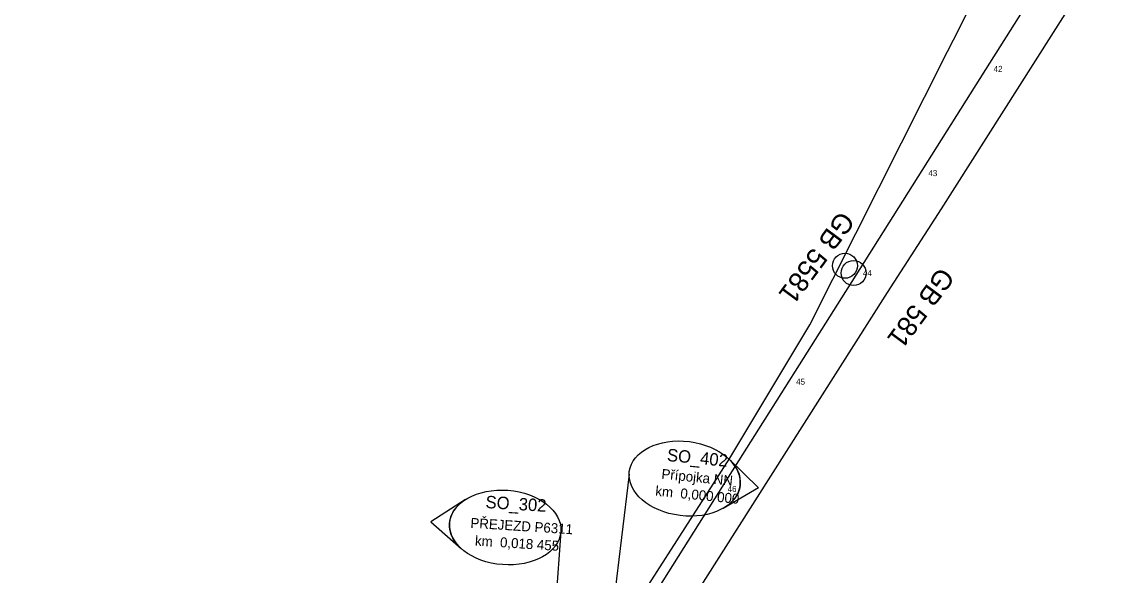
# Model space of a CAD drawing. Extents: x -743546 to -74, y -1128126 to -103.
# Drawn here: x -743267.3 to -743045.6, y -1127036 to -1126924.5 of the extents above; entities that cross this region are included whole.
import ezdxf

# ---------------------------------------------------------------- set-up
doc = ezdxf.new("R2010")
doc.units = 0
for name, color, linetype in [('_Násyp', 7, 'Continuous'), ('_Zabezpečovací zařízení_trasa', 7, 'Continuous'), ('bublina_fialová_čára_tenká', 7, 'Continuous'), ('bublina_růžová_230_čára_tučná', 7, 'Continuous'), ('křížky', 7, 'Continuous'), ('Vrstva 53', 7, 'Continuous'), ('Vrstva 60', 7, 'Continuous'), ('ŽBP', 7, 'Continuous')]:
    doc.layers.add(name, color=color, linetype=linetype)

# ---------------------------------------------------------------- blocks, each defined once
blk = doc.blocks.new('POINT_DISPLAY')
blk.add_line((0, 0), (0, 0))

msp = doc.modelspace()

# ---------------------------------------------------------------- linework, layer by layer
at = {"layer": '_Zabezpečovací zařízení_trasa'}
msp.add_lwpolyline([(-743049.28, -1126895.95), (-743072.49, -1126932.75), (-743098.65, -1126974.15), (-743125.94, -1127017.38), (-743152.6, -1127059.61), (-743175.02, -1127095.12), (-743199.16, -1127133.35), (-743215.97, -1127159.94), (-743232.82, -1127186.51), (-743247.46, -1127209.81), (-743254.52, -1127221.64), (-743261.3, -1127233.69), (-743264.16, -1127239.2), (-743264.86, -1127241.11), (-743267.34, -1127245.82)], dxfattribs=at)
at = {"layer": 'bublina_fialová_čára_tenká'}
for p, q in [((-743145.09, -1127015.48), (-743152.93, -1127080.48)), ((-743158.82, -1127027.04), (-743164.29, -1127099.42))]:
    msp.add_line(p, q, dxfattribs=at)
at = {"layer": 'bublina_růžová_230_čára_tučná'}
for p, q in [((-743124.92, -1127012.47), (-743119, -1127018.23)), ((-743124.92, -1127012.47), (-743119, -1127018.23)), ((-743119, -1127018.23), (-743126.16, -1127022.35)), ((-743119, -1127018.23), (-743126.16, -1127022.35)), ((-743178.06, -1127020.6), (-743185, -1127025.07)), ((-743178.06, -1127020.6), (-743185, -1127025.07)), ((-743185, -1127025.07), (-743178.81, -1127030.53)), ((-743185, -1127025.07), (-743178.81, -1127030.53))]:
    msp.add_line(p, q, dxfattribs=at)
for centre, major_axis in [((-743133.89, -1127016.36), (-11.16, 1.4)), ((-743170.04, -1127026.2), (11.22, -0.85))]:
    msp.add_ellipse(centre, major_axis=major_axis, ratio=0.666667, dxfattribs=at)
for centre, major_axis in [((-743133.89, -1127016.36), (11.16, -1.4)), ((-743170.04, -1127026.2), (-11.22, 0.85))]:
    msp.add_ellipse(centre, major_axis=major_axis, ratio=0.666473, start_param=5.557317, end_param=7.009053, dxfattribs=at)
at = {"layer": 'Vrstva 53'}
msp.add_lwpolyline([(-743032.8, -1126884.17), (-743063.8, -1126932.98), (-743082.27, -1126962.07), (-743093.1, -1126978.92), (-743136.47, -1127047.12), (-743147.78, -1127068.8), (-743159.64, -1127094.74), (-743160.17, -1127095.91), (-743166.78, -1127095.57), (-743176.42, -1127093.47), (-743180.17, -1127093.19), (-743180.08, -1127092.14), (-743178.51, -1127091.81), (-743175.35, -1127091.16), (-743150.08, -1127051.72), (-743124.8, -1127012.28), (-743108.67, -1126985.4), (-743080.97, -1126930.41), (-743079.79, -1126928.05), (-743048.51, -1126865.51)], dxfattribs=at)
at = {"layer": 'Vrstva 60'}
for p, q in [((-743072.49, -1126932.75), (-743072.49, -1126932.75)), ((-743085.57, -1126953.45), (-743085.57, -1126953.45)), ((-743098.65, -1126974.15), (-743098.65, -1126974.15)), ((-743112.29, -1126995.77), (-743112.29, -1126995.77)), ((-743125.94, -1127017.38), (-743125.94, -1127017.38))]:
    msp.add_line(p, q, dxfattribs=at)
at = {"layer": 'ŽBP'}
for centre in [(-743101.62, -1126973.52), (-743099.88, -1126974.98)]:
    msp.add_circle(centre, 2.52, dxfattribs=at)

# ---------------------------------------------------------------- block references
at = {"layer": 'křížky', "xscale": 10, "yscale": 10, "rotation": 61.14491455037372}
for p in [(-743072.49, -1126932.75), (-743085.57, -1126953.45), (-743098.65, -1126974.15), (-743112.29, -1126995.77), (-743125.94, -1127017.38)]:
    msp.add_blockref('POINT_DISPLAY', p, dxfattribs=at)

# ---------------------------------------------------------------- texts
at = {"layer": '_Násyp'}
for s, height, rotation, p in [('SO_402', 2.5, 354.3558, (-743137.54, -1127012.8)), ('Přípojka NN', 2, 354.3558, (-743138.64, -1127016.39)), ('km  0,000 000', 2, 354.3558, (-743139.87, -1127019.79)), ('SO_302', 2.5, 356.3528, (-743174.05, -1127022.28)), ('PŘEJEZD P6311', 2, 356.3528, (-743177.08, -1127026.26)), ('km  0,018 455', 2, 356.3528, (-743176.17, -1127029.83))]:
    msp.add_text(s, height=height, rotation=rotation, dxfattribs=at).set_placement(p)
at = {"layer": 'Vrstva 60'}
for s, p in [('42', (-743071.68, -1126934.49)), ('43', (-743084.82, -1126955.48)), ('44', (-743098, -1126975.59)), ('45', (-743111.46, -1126997.46)), ('46', (-743125.24, -1127019.04))]:
    msp.add_text(s, height=1.2, dxfattribs=at).set_placement(p)
at = {"layer": 'ŽBP'}
for s, p in [('GB 5581', (-743102.6, -1126962.25)), ('GB 581', (-743082.5, -1126973.56))]:
    msp.add_text(s, height=4, rotation=233.4505, dxfattribs=at).set_placement(p)

doc.saveas('drawing.dxf')
